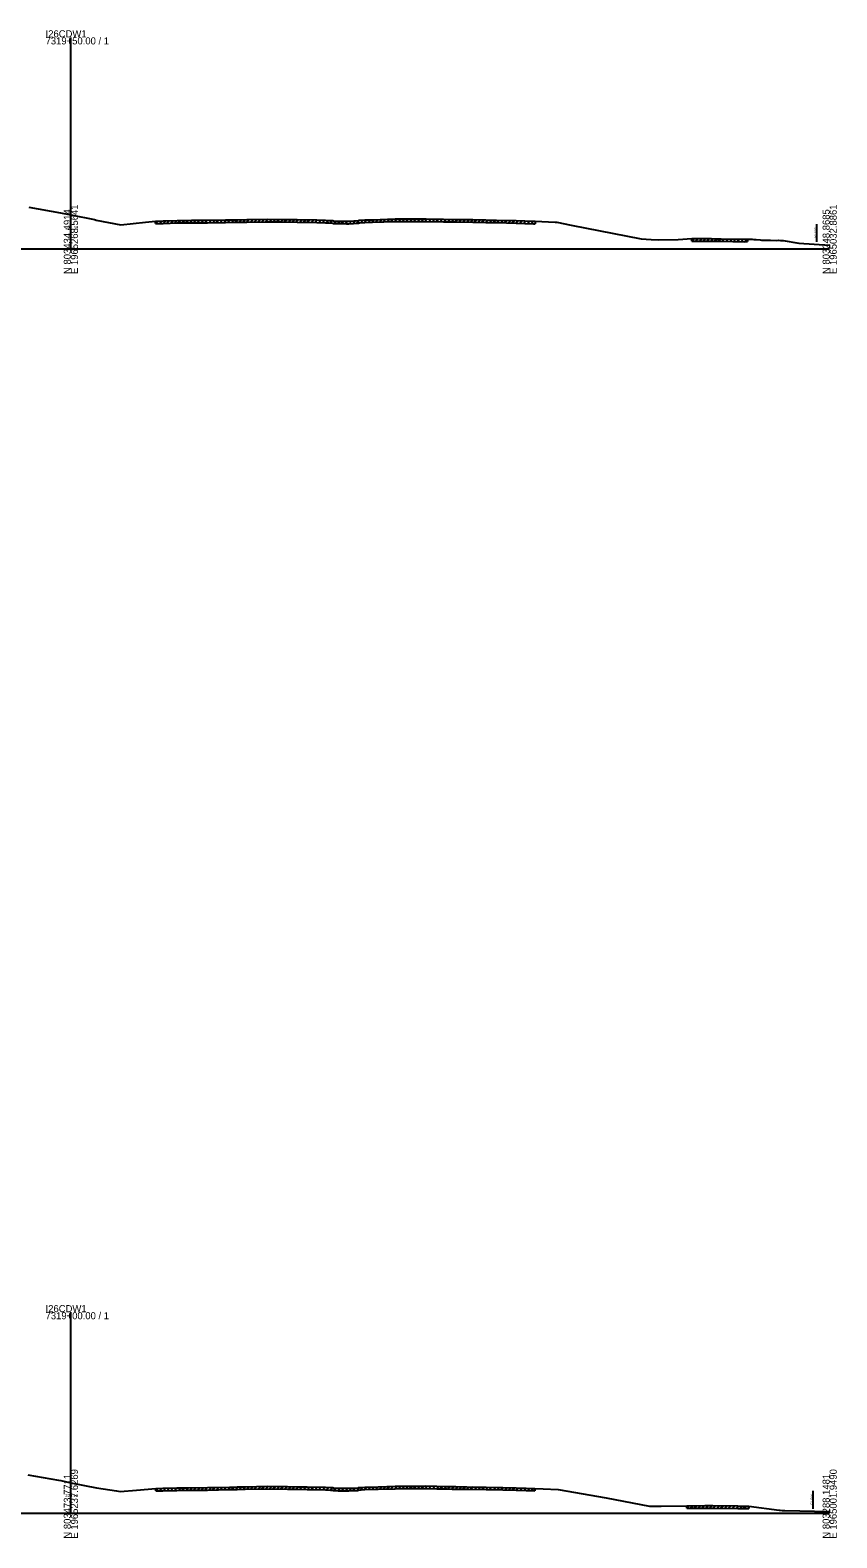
# Model space of a CAD drawing. Extents: x -26 to 1986619, y -10 to 827846.
# Drawn here: x 284 to 603, y -10 to 586 of the extents above; entities that cross this region are included whole.
import ezdxf

# ---------------------------------------------------------------- set-up
doc = ezdxf.new("R2010")
doc.units = 0
for name, color, linetype in [('RD_GPK_XS_Cell', 7, 'Continuous'), ('RD_XS_ExGround', 7, 'Continuous'), ('RD_XS_ExPaveRet', 7, 'Continuous'), ('RD_XS_ExRW', 7, 'Continuous'), ('RD_XS_TX_Elev_EX', 7, 'Continuous')]:
    doc.layers.add(name, color=color, linetype=linetype)

msp = doc.modelspace()

# ---------------------------------------------------------------- linework, layer by layer
at = {"layer": 'RD_GPK_XS_Cell'}
for p, q in [((300, 500), (300, 583.57)), ((0, 500), (300, 500)), ((300, 500), (600, 500)), ((300, 0), (300, 79.53)), ((0, 0), (300, 0)), ((300, 0), (600, 0))]:
    msp.add_line(p, q, dxfattribs=at)
at = {"layer": 'RD_XS_ExGround'}
for points in [[(283.42, 516.49), (295.91, 514.17), (300, 513.35), (309.31, 511.49), (309.7, 511.4), (310.04, 511.33), (319.72, 509.47), (329.54, 510.52), (333.49, 510.95), (336.48, 511.03), (341.98, 511.19), (347.73, 511.22), (353.96, 511.24), (361.15, 511.36), (365.92, 511.44), (369.6, 511.51), (377.71, 511.65), (383.15, 511.59), (389.5, 511.53), (397.24, 511.37), (400.74, 511.29), (401.98, 511.21), (403.51, 511.13), (403.82, 510.99), (404.83, 510.94), (405.67, 510.91), (406.56, 510.91), (407.09, 510.91), (408.96, 510.9), (409.92, 510.89), (413.74, 511.12), (413.94, 511.24), (414.25, 511.27), (416.28, 511.38), (419.3, 511.47), (428.25, 511.75), (434.38, 511.79), (440.44, 511.82), (447.37, 511.69), (452.54, 511.59), (458.97, 511.49), (464.11, 511.42), (468.34, 511.31), (476.01, 511.13), (482.94, 510.88), (483.59, 510.86), (491.48, 510.46), (492.17, 510.43), (497.78, 509.35), (525.52, 503.91), (529.41, 503.61), (532.23, 503.57), (540.08, 503.68), (545.48, 504), (553.25, 503.98), (555.71, 503.97), (557.06, 503.93), (566.21, 503.77), (567.53, 503.81), (569.4, 503.77), (569.97, 503.7), (570.99, 503.6), (572.55, 503.46), (573.06, 503.41), (576.61, 503.34), (579.07, 503.27), (579.77, 503.32), (580.62, 503.27), (581.04, 503.24), (581.67, 503.2), (587.87, 502.19), (600, 501.4)], [(282.98, 15.26), (295.05, 13.09), (295.97, 12.93), (300, 12.12), (310.13, 10.09), (318.01, 8.88), (319.52, 8.62), (326.01, 9.16), (333.53, 9.85), (336.41, 9.93), (341.88, 10.08), (346.23, 10.13), (353.99, 10.2), (362.66, 10.36), (365.78, 10.43), (368.97, 10.49), (377.68, 10.69), (385.63, 10.58), (389.29, 10.54), (393.47, 10.45), (400.74, 10.31), (402.6, 10.21), (403.54, 10.16), (403.81, 10.02), (404.47, 9.98), (405.74, 9.9), (406.57, 9.93), (407.05, 9.95), (408.78, 9.92), (409.92, 9.89), (411.42, 9.98), (413.64, 10.09), (413.78, 10.2), (414.71, 10.26), (416.26, 10.38), (421.53, 10.54), (428.16, 10.73), (434.39, 10.77), (440.36, 10.81), (444.7, 10.72), (448.68, 10.64), (450.7, 10.61), (452.18, 10.59), (456.56, 10.52), (464.19, 10.39), (470.77, 10.23), (476, 10.12), (479.96, 9.97), (483.43, 9.86), (486.78, 9.68), (492.72, 9.46), (511.58, 6.09), (528.82, 2.89), (533.33, 2.89), (543.49, 2.98), (550.63, 3.06), (553.76, 3.09), (563.65, 2.92), (564.58, 2.89), (565.35, 2.87), (566.88, 2.86), (568.05, 2.85), (580.06, 1.27), (580.45, 1.25), (581.26, 1.14), (582.31, 1.06), (600, 0.69)]]:
    msp.add_lwpolyline(points, dxfattribs=at)
at = {"layer": 'RD_XS_ExPaveRet'}
for p, q in [((333.49, 509.95), (334.52, 510.98)), ((333.49, 509.95), (333.49, 510.95)), ((333.49, 509.95), (336.48, 510.03)), ((334.99, 509.99), (336.02, 511.02)), ((336.48, 510.03), (341.98, 510.19)), ((336.49, 510.03), (337.52, 511.06)), ((337.99, 510.07), (339.02, 511.11)), ((339.49, 510.12), (340.52, 511.15)), ((340.99, 510.16), (342.02, 511.19)), ((341.98, 510.19), (347.73, 510.22)), ((342.49, 510.2), (343.5, 511.2)), ((343.99, 510.2), (345, 511.21)), ((345.49, 510.21), (346.5, 511.21)), ((346.99, 510.22), (348, 511.22)), ((347.73, 510.22), (353.96, 510.24)), ((348.49, 510.22), (349.5, 511.23)), ((349.99, 510.23), (351, 511.23)), ((351.49, 510.24), (352.5, 511.24)), ((352.99, 510.24), (354, 511.25)), ((353.96, 510.24), (361.15, 510.36)), ((354.49, 510.25), (355.51, 511.27)), ((355.99, 510.28), (357.01, 511.3)), ((357.49, 510.3), (358.51, 511.32)), ((358.99, 510.33), (360.01, 511.34)), ((360.49, 510.35), (361.51, 511.37)), ((361.15, 510.36), (365.92, 510.44)), ((361.99, 510.38), (363.01, 511.39)), ((363.49, 510.4), (364.51, 511.42)), ((364.99, 510.43), (366.01, 511.44)), ((365.92, 510.44), (369.6, 510.51)), ((366.49, 510.45), (367.51, 511.47)), ((367.99, 510.48), (369.01, 511.5)), ((369.49, 510.51), (370.51, 511.53)), ((369.6, 510.51), (377.71, 510.65)), ((370.99, 510.54), (372.01, 511.56)), ((372.49, 510.56), (373.51, 511.58)), ((373.99, 510.59), (375.01, 511.61)), ((375.49, 510.62), (376.51, 511.63)), ((376.99, 510.64), (378, 511.65)), ((377.71, 510.65), (383.15, 510.59)), ((378.49, 510.65), (379.48, 511.63)), ((379.99, 510.63), (380.98, 511.62)), ((381.49, 510.61), (382.48, 511.6)), ((382.99, 510.6), (383.98, 511.58)), ((383.15, 510.59), (389.5, 510.53)), ((384.49, 510.58), (385.48, 511.57)), ((385.99, 510.56), (386.98, 511.55)), ((387.49, 510.55), (388.48, 511.54)), ((388.99, 510.53), (389.98, 511.52)), ((389.5, 510.53), (397.24, 510.37)), ((390.49, 510.51), (391.47, 511.49)), ((391.99, 510.48), (392.97, 511.46)), ((393.49, 510.45), (394.47, 511.43)), ((394.99, 510.42), (395.97, 511.4)), ((396.49, 510.39), (397.47, 511.37)), ((397.24, 510.37), (400.74, 510.29)), ((397.99, 510.35), (398.97, 511.33)), ((399.49, 510.32), (400.47, 511.3)), ((400.74, 510.29), (401.98, 510.21)), ((400.99, 510.28), (401.93, 511.22)), ((401.98, 510.21), (403.51, 510.13)), ((402.49, 510.18), (403.44, 511.13)), ((403.51, 510.13), (403.82, 509.99)), ((403.82, 509.99), (404.83, 509.94)), ((403.99, 509.98), (404.95, 510.94)), ((404.83, 509.94), (405.67, 509.91)), ((405.49, 509.92), (406.49, 510.91)), ((405.67, 509.91), (406.56, 509.91)), ((406.56, 509.91), (407.09, 509.91)), ((406.99, 509.91), (407.99, 510.9)), ((407.09, 509.91), (408.96, 509.9)), ((408.49, 509.9), (409.48, 510.89)), ((408.96, 509.9), (409.92, 509.89)), ((409.92, 509.89), (413.74, 510.12)), ((409.99, 509.89), (411.06, 510.96)), ((411.49, 509.98), (412.56, 511.05)), ((412.99, 510.08), (414.18, 511.26)), ((413.74, 510.12), (413.94, 510.24)), ((413.94, 510.24), (414.25, 510.27)), ((414.25, 510.27), (416.28, 510.38)), ((414.49, 510.28), (415.55, 511.34)), ((415.99, 510.36), (417.03, 511.4)), ((416.28, 510.38), (419.3, 510.47)), ((417.49, 510.42), (418.52, 511.45)), ((418.99, 510.46), (420.02, 511.5)), ((419.3, 510.47), (428.25, 510.75)), ((420.49, 510.51), (421.52, 511.54)), ((421.99, 510.56), (423.02, 511.59)), ((423.49, 510.6), (424.52, 511.64)), ((424.99, 510.65), (426.02, 511.68)), ((426.49, 510.7), (427.52, 511.73)), ((427.99, 510.74), (429, 511.76)), ((428.25, 510.75), (434.38, 510.79)), ((429.49, 510.76), (430.5, 511.77)), ((430.99, 510.77), (432, 511.78)), ((432.49, 510.78), (433.5, 511.79)), ((433.99, 510.79), (435, 511.79)), ((434.38, 510.79), (440.44, 510.82)), ((435.49, 510.8), (436.5, 511.8)), ((436.99, 510.8), (438, 511.81)), ((438.49, 510.81), (439.5, 511.82)), ((439.99, 510.82), (440.98, 511.81)), ((440.44, 510.82), (447.37, 510.69)), ((441.49, 510.8), (442.47, 511.78)), ((442.99, 510.77), (443.97, 511.75)), ((444.49, 510.74), (445.47, 511.73)), ((445.99, 510.72), (446.97, 511.7)), ((447.37, 510.69), (452.54, 510.59)), ((447.49, 510.69), (448.47, 511.67)), ((448.99, 510.66), (449.97, 511.64)), ((450.49, 510.63), (451.47, 511.61)), ((451.99, 510.6), (452.97, 511.59)), ((452.54, 510.59), (458.97, 510.49)), ((453.49, 510.58), (454.48, 511.56)), ((454.99, 510.56), (455.98, 511.54)), ((456.49, 510.53), (457.48, 511.52)), ((457.99, 510.51), (458.98, 511.49)), ((458.97, 510.49), (464.11, 510.42)), ((459.49, 510.48), (460.48, 511.47)), ((460.99, 510.46), (461.98, 511.45)), ((462.49, 510.44), (463.48, 511.43)), ((463.99, 510.42), (464.97, 511.4)), ((464.11, 510.42), (468.34, 510.31)), ((465.49, 510.38), (466.47, 511.36)), ((466.99, 510.35), (467.97, 511.32)), ((468.34, 510.31), (476.01, 510.13)), ((468.49, 510.31), (469.47, 511.28)), ((469.99, 510.27), (470.97, 511.25)), ((471.49, 510.24), (472.47, 511.21)), ((472.99, 510.2), (473.97, 511.18)), ((474.49, 510.17), (475.47, 511.14)), ((475.99, 510.13), (476.96, 511.1)), ((476.01, 510.13), (482.94, 509.88)), ((477.49, 510.08), (478.46, 511.04)), ((478.99, 510.02), (479.96, 510.99)), ((480.49, 509.97), (481.46, 510.93)), ((481.99, 509.92), (482.96, 510.88)), ((482.94, 509.88), (483.59, 509.86)), ((483.59, 510.86), (483.59, 509.86)), ((545.48, 503), (546.47, 504)), ((545.48, 503), (545.48, 504)), ((545.48, 503), (553.25, 502.98)), ((546.98, 503), (547.97, 504)), ((548.48, 502.99), (549.47, 503.99)), ((549.98, 502.99), (550.97, 503.98)), ((551.48, 502.98), (552.47, 503.98)), ((552.98, 502.98), (553.97, 503.97)), ((553.25, 502.98), (555.71, 502.97)), ((554.48, 502.97), (555.47, 503.97)), ((555.71, 502.97), (557.06, 502.93)), ((555.98, 502.96), (556.95, 503.93)), ((557.06, 502.93), (566.21, 502.77)), ((557.48, 502.92), (558.46, 503.91)), ((558.98, 502.9), (559.96, 503.88)), ((560.48, 502.87), (561.46, 503.85)), ((561.98, 502.85), (562.96, 503.83)), ((563.48, 502.82), (564.46, 503.8)), ((564.98, 502.79), (565.96, 503.78)), ((566.21, 502.77), (567.53, 502.81)), ((566.48, 502.78), (567.5, 503.81)), ((567.53, 503.81), (567.53, 502.81)), ((333.53, 8.85), (334.56, 9.88)), ((333.53, 8.85), (333.53, 9.85)), ((333.53, 8.85), (336.41, 8.93)), ((335.03, 8.89), (336.06, 9.92)), ((336.41, 8.93), (341.88, 9.08)), ((336.53, 8.94), (337.55, 9.96)), ((338.03, 8.98), (339.05, 10)), ((339.53, 9.02), (340.55, 10.05)), ((341.03, 9.06), (342.05, 10.08)), ((341.88, 9.08), (346.23, 9.13)), ((342.53, 9.09), (343.54, 10.1)), ((344.03, 9.11), (345.04, 10.12)), ((345.53, 9.12), (346.54, 10.13)), ((346.23, 9.13), (353.99, 9.2)), ((347.03, 9.14), (348.03, 10.15)), ((348.53, 9.15), (349.53, 10.16)), ((350.03, 9.17), (351.03, 10.17)), ((351.53, 9.18), (352.53, 10.19)), ((353.03, 9.19), (354.04, 10.2)), ((353.99, 9.2), (362.66, 9.36)), ((354.53, 9.21), (355.54, 10.23)), ((356.03, 9.24), (357.04, 10.26)), ((357.53, 9.26), (358.54, 10.28)), ((359.03, 9.29), (360.04, 10.31)), ((360.53, 9.32), (361.54, 10.34)), ((362.03, 9.35), (363.05, 10.37)), ((362.66, 9.36), (365.78, 9.43)), ((363.53, 9.38), (364.55, 10.4)), ((365.03, 9.41), (366.05, 10.43)), ((365.78, 9.43), (368.97, 9.49)), ((366.53, 9.44), (367.55, 10.46)), ((368.03, 9.47), (369.05, 10.49)), ((368.97, 9.49), (377.68, 9.69)), ((369.53, 9.5), (370.55, 10.52)), ((371.03, 9.53), (372.05, 10.56)), ((372.53, 9.57), (373.55, 10.59)), ((374.03, 9.6), (375.05, 10.63)), ((375.53, 9.64), (376.55, 10.66)), ((377.03, 9.67), (378.04, 10.68)), ((377.68, 9.69), (385.63, 9.58)), ((378.53, 9.67), (379.51, 10.66)), ((380.03, 9.65), (381.01, 10.64)), ((381.53, 9.63), (382.51, 10.62)), ((383.03, 9.62), (384.01, 10.6)), ((384.53, 9.6), (385.51, 10.58)), ((385.63, 9.58), (389.29, 9.54)), ((386.03, 9.58), (387.02, 10.57)), ((387.53, 9.56), (388.52, 10.55)), ((389.03, 9.55), (390.01, 10.53)), ((389.29, 9.54), (393.47, 9.45)), ((390.53, 9.52), (391.5, 10.5)), ((392.03, 9.48), (393, 10.46)), ((393.47, 9.45), (400.74, 9.31)), ((393.53, 9.45), (394.51, 10.43)), ((395.03, 9.42), (396.01, 10.4)), ((396.53, 9.39), (397.51, 10.37)), ((398.03, 9.36), (399.01, 10.34)), ((399.53, 9.33), (400.51, 10.31)), ((400.74, 9.31), (402.6, 9.21)), ((401.03, 9.29), (401.98, 10.24)), ((402.53, 9.21), (403.48, 10.16)), ((402.6, 9.21), (403.54, 9.16)), ((403.54, 9.16), (403.81, 9.02)), ((403.81, 9.02), (404.47, 8.98)), ((404.03, 9.01), (404.97, 9.95)), ((404.47, 8.98), (405.74, 8.9)), ((405.53, 8.92), (406.54, 9.93)), ((405.74, 8.9), (406.57, 8.93)), ((406.57, 8.93), (407.05, 8.95)), ((407.03, 8.95), (408.01, 9.93)), ((407.05, 8.95), (408.78, 8.92)), ((408.53, 8.92), (409.51, 9.9)), ((408.78, 8.92), (409.92, 8.89)), ((409.92, 8.89), (411.42, 8.98)), ((410.03, 8.9), (411.09, 9.96)), ((411.42, 8.98), (413.64, 9.09)), ((411.53, 8.99), (412.58, 10.04)), ((413.03, 9.06), (414.19, 10.23)), ((413.64, 9.09), (413.78, 9.2)), ((413.78, 9.2), (414.71, 9.26)), ((414.53, 9.25), (415.61, 10.33)), ((414.71, 9.26), (416.26, 9.38)), ((416.03, 9.36), (417.07, 10.4)), ((416.26, 9.38), (421.53, 9.54)), ((417.53, 9.42), (418.56, 10.45)), ((419.03, 9.46), (420.06, 10.49)), ((420.53, 9.51), (421.56, 10.54)), ((421.53, 9.54), (428.16, 9.73)), ((422.03, 9.55), (423.06, 10.58)), ((423.53, 9.59), (424.56, 10.62)), ((425.03, 9.64), (426.06, 10.67)), ((426.53, 9.68), (427.56, 10.71)), ((428.03, 9.72), (429.04, 10.73)), ((428.16, 9.73), (434.39, 9.77)), ((429.53, 9.74), (430.53, 10.74)), ((431.03, 9.75), (432.03, 10.75)), ((432.53, 9.76), (433.53, 10.76)), ((434.03, 9.77), (435.03, 10.77)), ((434.39, 9.77), (440.36, 9.81)), ((435.53, 9.78), (436.53, 10.78)), ((437.03, 9.79), (438.03, 10.79)), ((438.53, 9.8), (439.53, 10.8)), ((440.03, 9.81), (441.01, 10.8)), ((440.36, 9.81), (444.7, 9.72)), ((441.53, 9.79), (442.51, 10.76)), ((443.03, 9.75), (444.01, 10.73)), ((444.53, 9.72), (445.51, 10.7)), ((444.7, 9.72), (448.68, 9.64)), ((446.03, 9.69), (447.01, 10.67)), ((447.53, 9.66), (448.51, 10.64)), ((448.68, 9.64), (450.7, 9.61)), ((449.03, 9.63), (450.01, 10.62)), ((450.53, 9.61), (451.51, 10.6)), ((450.7, 9.61), (452.18, 9.59)), ((452.03, 9.59), (453.01, 10.58)), ((452.18, 9.59), (456.56, 9.52)), ((453.53, 9.57), (454.51, 10.55)), ((455.03, 9.54), (456.01, 10.53)), ((456.53, 9.52), (457.51, 10.5)), ((456.56, 9.52), (464.19, 9.39)), ((458.03, 9.49), (459.01, 10.48)), ((459.53, 9.47), (460.51, 10.45)), ((461.03, 9.44), (462.01, 10.43)), ((462.53, 9.42), (463.51, 10.4)), ((464.03, 9.39), (465, 10.37)), ((464.19, 9.39), (470.77, 9.23)), ((465.53, 9.36), (466.5, 10.33)), ((467.03, 9.32), (468, 10.3)), ((468.53, 9.28), (469.5, 10.26)), ((470.03, 9.24), (471, 10.22)), ((470.77, 9.23), (476, 9.12)), ((471.53, 9.21), (472.51, 10.19)), ((473.03, 9.18), (474.01, 10.16)), ((474.53, 9.15), (475.51, 10.13)), ((476, 9.12), (479.96, 8.97)), ((476.03, 9.12), (476.99, 10.08)), ((477.53, 9.06), (478.49, 10.02)), ((479.03, 9), (479.99, 9.97)), ((479.96, 8.97), (483.43, 8.86)), ((480.53, 8.95), (481.5, 9.92)), ((482.03, 8.91), (483, 9.88)), ((483.43, 9.86), (483.43, 8.86)), ((543.49, 1.98), (544.5, 2.99)), ((543.49, 1.98), (543.49, 2.98)), ((543.49, 1.98), (550.63, 2.06)), ((544.99, 2), (546, 3.01)), ((546.49, 2.01), (547.5, 3.02)), ((547.99, 2.03), (549, 3.04)), ((549.49, 2.05), (550.5, 3.06)), ((550.63, 2.06), (553.76, 2.09)), ((550.99, 2.06), (552.01, 3.07)), ((552.49, 2.08), (553.51, 3.09)), ((553.76, 2.09), (563.65, 1.92)), ((553.99, 2.09), (554.98, 3.07)), ((555.49, 2.06), (556.48, 3.05)), ((556.99, 2.04), (557.98, 3.02)), ((558.49, 2.01), (559.48, 2.99)), ((559.99, 1.98), (560.98, 2.96)), ((561.49, 1.95), (562.48, 2.94)), ((562.99, 1.93), (563.97, 2.91)), ((563.65, 1.92), (564.58, 1.89)), ((564.49, 1.89), (565.47, 2.87)), ((564.58, 1.89), (565.35, 1.87)), ((565.35, 1.87), (566.88, 1.86)), ((565.99, 1.87), (566.99, 2.86)), ((566.88, 1.86), (568.05, 1.85)), ((568.05, 2.85), (568.05, 1.85))]:
    msp.add_line(p, q, dxfattribs=at)
at = {"layer": 'RD_XS_ExRW'}
for p, q in [((594.92, 502.73), (594.92, 509.73)), ((593.52, 1.83), (593.52, 8.83))]:
    msp.add_line(p, q, dxfattribs=at)

# ---------------------------------------------------------------- texts
at = {"layer": 'RD_GPK_XS_Cell'}
for s, p in [('I26CDW1', (290, 583.57)), ('7319+50.00 / 1', (290, 580.77)), ('7319+00.00 / 1', (290, 76.73)), ('I26CDW1', (290, 79.53))]:
    msp.add_text(s, height=2.8, dxfattribs=at).set_placement(p)
for s, p in [('N 803434.4914', (300, 490)), ('E 1965268.5641', (302.8, 490)), ('N 803248.8685', (600, 490)), ('E 1965032.8861', (602.8, 490)), ('N 803473.7711', (300, -10)), ('E 1965237.6269', (302.8, -10)), ('N 803288.1481', (600, -10)), ('E 1965001.9490', (602.8, -10))]:
    msp.add_text(s, height=2.8, rotation=90, dxfattribs=at).set_placement(p)
at = {"layer": 'RD_XS_ExRW'}
for p in [(594.67, 504.42), (593.27, 3.51)]:
    msp.add_text('EX. R/W ', height=0.75, rotation=90, dxfattribs=at).set_placement(p)
at = {"layer": 'RD_XS_TX_Elev_EX'}
for s, p in [('221.35', (297.85, 507.65)), ('220.12', (297.76, 6.42))]:
    msp.add_text(s, height=1.2, dxfattribs=at).set_placement(p)

doc.saveas('drawing.dxf')
